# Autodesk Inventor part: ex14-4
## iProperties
Author: J. DESIGNER
Revision Number: A
Shininess: 64.0
Angle Display Precision: 2
Document Length Units: 11272
Document Angle Units: 11286
Document Time Units: 11279
Document Mass Units: 11290
Document Length Units Precision: 3
Document Angle Units Precision: 2
Compacted: False
PropertySet Name: _Private Model Information
Created: 2001-10
Part Number: ex14-4
Description: RISER BAR
Document SubType Name: Modeling
Designer: J. DESIGNER
Control State: 0
Master: False
Checked Out: False
PropertySet Name: Design Tracking Control
Density: 0.0
Volumn: 0.0
Area: 0.0
PropertySet Name: Model Information
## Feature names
1. Extrusion1
2. Extrusion4
3. Hole1
4. Hole2
